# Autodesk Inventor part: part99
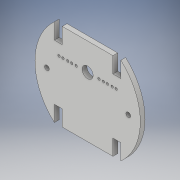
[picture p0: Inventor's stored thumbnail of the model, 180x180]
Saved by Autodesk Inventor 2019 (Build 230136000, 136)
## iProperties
Created: 2020-02
Part Number: part99
Material: Generic
Document SubType Name: Modeling
Designer: shivu
Density: 1 g/cm^3
Appearance: Default
Author: shivu
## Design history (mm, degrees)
sketch "Sketch1"
  geometry: L1 (5, 45.06)-(5, 35.06); L2 (0, 35.06)-(0, 45.06); L3 (0, 35.06)-(0, 45.06); L4 (37, 45.06)-(37, 35.06); L5 (42, 35.06)-(42, 45.06); L6 (42, 35.06)-(37, 35.06); L7 (5, 35.06)-(0, 35.06); L8 (37, -10)-(37, 0); L9 (5, -10)-(5, 0); L10 (42, 0)-(37, 0); L11 (42, 0)-(42, -10); L12 (5, 0)-(0, 0); L13 (0, 0)-(5, 0); L14 (37, 0)-(42, 0); L15 (5, 45.06)-(37, 45.06); L16 (5, -10)-(37, -10); L17 (0, 0)-(0, -10); C1 r 3.5 at (21, 27.924); C2 r 0.75 at (28.208, 27.924); C3 r 0.75 at (31.02, 27.924); C4 r 0.75 at (33.511, 27.924); C5 r 0.75 at (36.542, 27.924); C6 r 0.75 at (39.033, 27.924); C7 r 1.5 at (46.689, 17.53); C8 r 0.75 at (13.792, 27.924); C9 r 0.75 at (10.98, 27.924); C10 r 0.75 at (8.489, 27.924); C11 r 0.75 at (5.458, 27.924); C12 r 0.75 at (2.967, 27.924); C13 r 1.5 at (-4.689, 17.53); A1 r 37.095 centre (17.137, 17.53) between (42, -10) and (42, 45.06); A2 r 37.095 centre (24.863, 17.53) between (0, 45.06) and (0, -10)
  constraints: 34 end point, 15 centre point, 4 horizontal, 4 parallel, 4 point on circle, 1 vertical
extrude "Extrusion3" new body sketch "Sketch1" distance "d65" = 3; taper "d66" = 0 deg
body "Solid2"
